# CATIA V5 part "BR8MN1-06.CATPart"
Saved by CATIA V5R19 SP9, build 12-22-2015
Part number: BR8MN1-06
Definition: design
Nomenclature: BR8MN1-06
Source: Unknown
Bounding box of the stored display mesh (mm): x -4.6 to 7.9, y 0 to 12, z 0 to 30.48
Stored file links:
  Z:\charly_robot\BR8MN1-06.CATPart
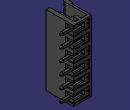
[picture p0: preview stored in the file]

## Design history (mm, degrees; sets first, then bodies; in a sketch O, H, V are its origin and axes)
AxisSystem1: origin (0, 0, 0), X (1, 0, 0), Y (0, 1, 0), Z (0, 0, 1)
Body1 "MANIFOLD_SOLID_BREP #202339" (main body)
  Solid1: solid without history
